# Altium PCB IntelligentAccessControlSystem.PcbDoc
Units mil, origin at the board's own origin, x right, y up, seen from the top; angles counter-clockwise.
Board outline 3020 x 3355 mil, 2 copper layers (Top Layer, Bottom Layer); 10 components, 8 nets, 88 pads, 0 vias.
Unrouted connection lines stored in the file: 2.
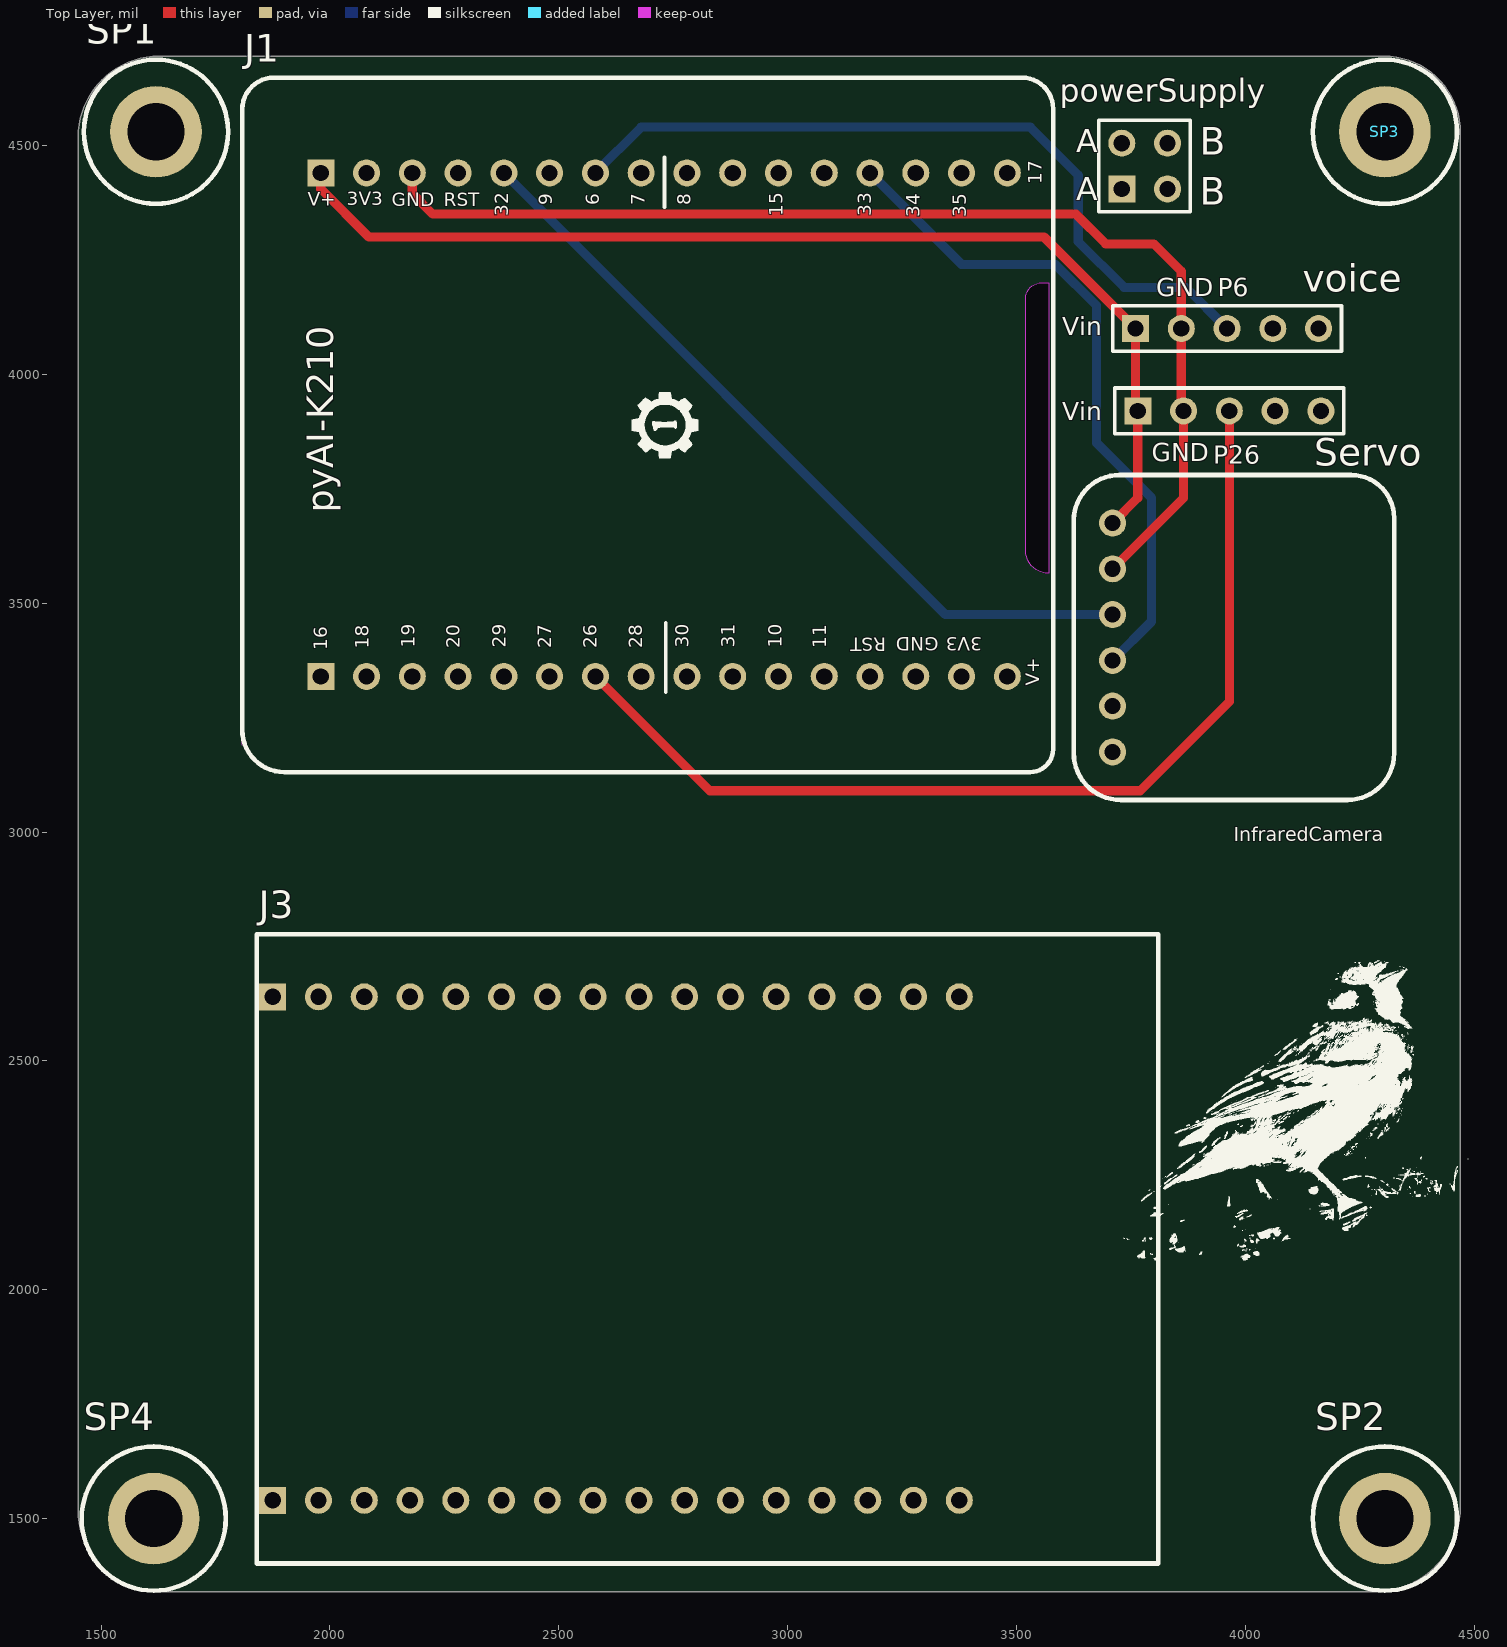
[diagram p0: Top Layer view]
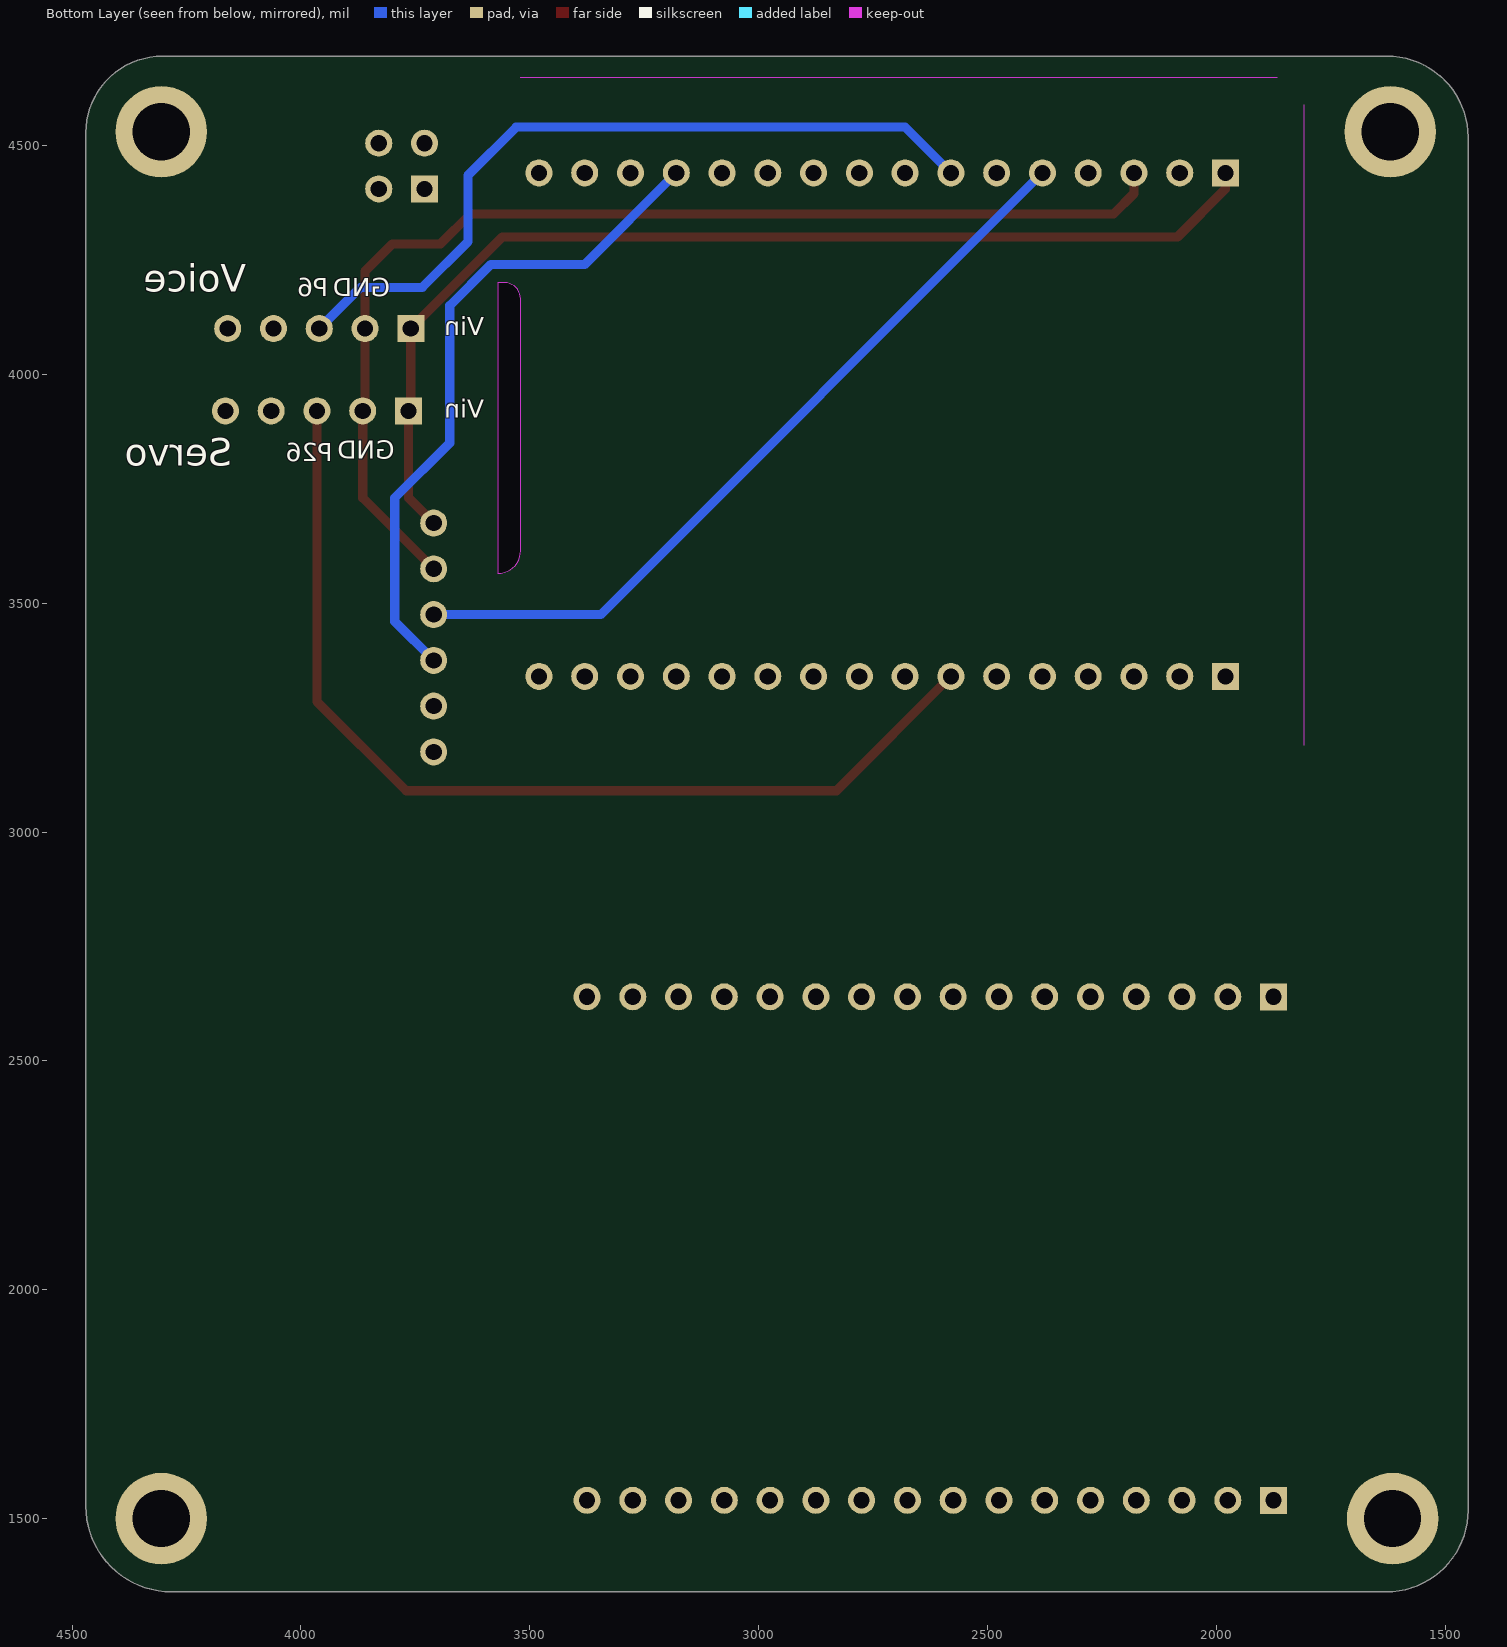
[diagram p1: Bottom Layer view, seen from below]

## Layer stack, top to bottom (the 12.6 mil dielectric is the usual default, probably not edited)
Top Solder: solder mask 0.4, Solder Resist, Dk 3.5
Top Layer: signal copper 1.4
Dielectric 1: dielectric 12.6, FR-4, Dk 4.8
Bottom Layer: signal copper 1.4
Bottom Solder: solder mask 0.4, Solder Resist, Dk 3.5

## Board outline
1450,1518.48 1450,4517.89 cw(c1627.11,4517.89) 1627.11,4695 4302.55,4695 cw(c4302.55,4527.55) 4470,4527.55 4470,1527.46 cw(c4282.54,1527.46) 4282.54,1340 1628.48,1340 cw(c1628.48,1518.48)
cut-out: 3570,3565 cw(c3570,3615) 3520,3615 3520,4165 cw(c3555,4165) 3555,4200 3570,4200

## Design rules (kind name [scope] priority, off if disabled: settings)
Clearance [All] p1: gap=10 ignorepadtopadclearanceinfootprint=FALSE except(0: Arc-Hole Track-Hole SMDPad-Hole THPad-Hole Via-Hole Fill-Hole Poly-Hole Region-Hole Text-Hole)
PolygonConnect [All] p1: connectstyle=Relief reliefconductorwidth=10 reliefentries=4 polygonreliefangle="90 Angle" airgapwidth=10
RoutingVias [All] p1: holewidth=28 width=50 viastyle="Through Hole" minholewidth=28 minwidth=50 maxholewidth=28 maxwidth=50
SolderMaskExpansion [All] p1: expansion=4
Width [All] p1: maxlimit=30 minlimit=20 preferedwidth=20 minimp=50.000000 maximp=50.000000 favimp=50.000000
30 further rules are at their usual default settings.

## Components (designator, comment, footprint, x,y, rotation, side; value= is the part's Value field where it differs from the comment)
InfraredCamera "InfraredCamera" InfraredCamera 3620,3795 r270 top (schematic designator J2)
J1 "K210-Main-Board" K210-Main-Board 2730,3890 r90 top
J3 "LCD" LCD 3810,1401.78 r90 top
powerSupply "Additional power supply" HDR2X2 3730,4405 r0 top (schematic designator P2)
Servo "Servo" HDR1X5 3765,3920 r0 top (schematic designator P3)
SP1 "M3铜柱" M3x4_L 1620,4530 r0 top
SP2 "M3铜柱" M3x4_L 4305,1500 r0 top
SP3 "M3铜柱" M3x4_L 4305,4530 r0 top
SP4 "M3铜柱" M3x4_L 1615,1500 r0 top
voice "voice broadcast" HDR1X5 3760,4100 r0 top (schematic designator P1)

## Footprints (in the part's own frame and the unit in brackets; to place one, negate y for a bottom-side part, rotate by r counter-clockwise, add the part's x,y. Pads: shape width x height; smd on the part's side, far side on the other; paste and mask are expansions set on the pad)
HDR1X5 [mm] "Connector; Header; 5 Position"
  rect 1.5x1.5 hole 0.9: 1(0,0)
  round 1.5 hole 0.9: 2(2.54,0) 3(5.08,0) 4(7.62,0) 5(10.16,0)
  silkscreen extent -1.27,-1.27 11.43,1.27
HDR2X2 [mm] "Connector; Header; 2x2 Position"
  rect 1.5x1.5 hole 0.9: 1(0,0)
  round 1.5 hole 0.9: 2(0,2.54) 3(2.54,0) 4(2.54,2.54)
  silkscreen extent -1.27,-1.27 3.81,3.81
InfraredCamera [mm]
  round 1.5 hole 0.9: 1(3.048,2.286) 2(5.588,2.286) 3(8.128,2.286) 4(10.668,2.286) 5(13.208,2.286) 6(15.748,2.286)
  silkscreen extent 0.38,0.13 18.41,17.91
K210-Main-Board [mm]
  rect 1.5x1.5 hole 0.9: 1(-13.97,19.05) 32(13.97,19.05)
  round 1.5 hole 0.9: 2(-13.97,16.51) 3(-13.97,13.97) 4(-13.97,11.43) 5(-13.97,8.89) 6(-13.97,6.35) 7(-13.97,3.81) 8(-13.97,1.27) 9(-13.97,-1.27) 10(-13.97,-3.81) 11(-13.97,-6.35) 12(-13.97,-8.89) 13(-13.97,-11.43) 14(-13.97,-13.97) 15(-13.97,-16.51) 16(-13.97,-19.05) 17(13.97,-19.05) 18(13.97,-16.51) 19(13.97,-13.97) 20(13.97,-11.43) 21(13.97,-8.89) 22(13.97,-6.35) 23(13.97,-3.81) 24(13.97,-1.27) 25(13.97,1.27) 26(13.97,3.81) 27(13.97,6.35) 28(13.97,8.89) 29(13.97,11.43) 30(13.97,13.97) 31(13.97,16.51)
  Keep-Out Layer lines w0: -17.779,23.41 17.761,23.41 ; 19.261,21.91 19.261,-20.09
  silkscreen extent -19.28,-21.59 19.26,23.41
LCD [mm]
  rect 1.5x1.5 hole 0.9: 1(3.511,49.149) 32(31.451,49.149)
  round 1.5 hole 0.9: 2(3.511,46.609) 3(3.511,44.069) 4(3.511,41.529) 5(3.511,38.989) 6(3.511,36.449) 7(3.511,33.909) 8(3.511,31.369) 9(3.511,28.829) 10(3.511,26.289) 11(3.511,23.749) 12(3.511,21.209) 13(3.511,18.669) 14(3.511,16.129) 15(3.511,13.589) 16(3.511,11.049) 17(31.451,11.049) 18(31.451,13.589) 19(31.451,16.129) 20(31.451,18.669) 21(31.451,21.209) 22(31.451,23.749) 23(31.451,26.289) 24(31.451,28.829) 25(31.451,31.369) 26(31.451,33.909) 27(31.451,36.449) 28(31.451,38.989) 29(31.451,41.529) 30(31.451,44.069) 31(31.451,46.609)
  silkscreen extent 0,0 34.92,50.04
M3x4_L [mil] "M3铜柱，长：4mm"
  round 200 hole 125: 1(0,0)
  silkscreen extent -157,-157 157,157, body extent -106,-93 106,93, height 159

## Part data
powerSupply: library part "Header 2X2", "Header, 2-Pin, Dual row"
Servo voice: library part "Header 5", "Header, 5-Pin"
SP1 SP2 SP3 SP4: library part 铜柱小焊盘, "铜柱"

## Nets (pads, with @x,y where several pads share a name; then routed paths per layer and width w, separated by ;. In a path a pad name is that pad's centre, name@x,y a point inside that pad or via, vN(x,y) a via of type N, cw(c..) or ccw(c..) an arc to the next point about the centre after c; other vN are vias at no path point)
6: J1.26 voice.3 | length 1688.6
  Bottom Layer w20: J1.26 2680,4540 3530,4540 3635,4435 3635,4290 3735,4190 3870,4190 voice.3
26: J1.7 Servo.3 | length 2204.3
  Top Layer w20: J1.7 2830,3090 3770,3090 3965,3285 Servo.3
GND: InfraredCamera.2 J1.30 Servo.2 voice.2 | length 2511.7
  Top Layer w20: J1.30 2180,4395 2225,4350 3630,4350 3695,4285 3800,4285 3860,4225 voice.2 3860,3925 Servo.2 3865,3730 InfraredCamera.2
NetP2_1: powerSupply.1 powerSupply.2
NetP2_3: powerSupply.3 powerSupply.4
SCL: InfraredCamera.3 J1.28 | length 1729.7
  Bottom Layer w20: J1.28 3345,3475 InfraredCamera.3
SDA: InfraredCamera.4 J1.20 | length 1475
  Bottom Layer w20: J1.20 3380,4240 3585,4240 3675,4150 3675,3850 3795,3730 3795,3460 InfraredCamera.4
Vin: InfraredCamera.1 J1.32 Servo.1 voice.1 | length 2391.2
  Top Layer w20: J1.32 1980,4405 2085,4300 3560,4300 voice.1 3760,3925 Servo.1 3765,3730 InfraredCamera.1
pads on no net: InfraredCamera.5 InfraredCamera.6 J1.1 J1.2 J1.3 J1.4 J1.5 J1.6 J1.8 J1.9 J1.10 J1.11 J1.12 J1.13 J1.14 J1.15 J1.16 J1.17 J1.18 J1.19 J1.21 J1.22 J1.23 J1.24 J1.25 J1.27 J1.29 J1.31 J3.1 J3.2 J3.3 J3.4 J3.5 J3.6 J3.7 J3.8 J3.9 J3.10 J3.11 J3.12 J3.13 J3.14 J3.15 J3.16 J3.17 J3.18 J3.19 J3.20 J3.21 J3.22 J3.23 J3.24 J3.25 J3.26 J3.27 J3.28 J3.29 J3.30 J3.31 J3.32 Servo.4 Servo.5 SP1.1 SP2.1 SP3.1 SP4.1 voice.4 voice.5

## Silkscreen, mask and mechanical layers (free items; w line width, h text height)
Top Overlay:
  drawing of 5566 lines, arcs and shapes, not listed
  text "B" at 3900,4480 h60
  text "GND" at 3805,4170 h40
  text "P6" at 3940,4170 h40
  text "Vin" at 3600,4085 h40
  text "Vin" at 3600,3900 h40
  text "GND" at 3795,3810 h40
  text "P26" at 3930,3805 h40
Bottom Overlay:
  text "Voice" at 4120,4180 h60
  text "GND" at 3805,4170 h40
  text "P6" at 3940,4170 h40
  text "Vin" at 3600,4085 h40
  text "Vin" at 3600,3905 h40
  text "GND" at 3795,3815 h40
  text "P26" at 3930,3810 h40
  text "Servo" at 4150,3800 h60
Mechanical 1:
  lines w10: 1450,1518.48 ccw(c1628.48,1518.48) 1628.48,1340 4175,1340 4282.54,1340 ccw(c4282.54,1527.46) 4470,1527.46 4470,4400 4470,4527.55 ccw(c4302.55,4527.55) 4302.55,4695 1910,4695 1627.11,4695 ccw(c1627.11,4517.89) 1450,4517.89 1450,3700 1450,1518.48 ; 3520,3615 ccw(c3570,3615) 3570,3565 3570,4200 3555,4200 ccw(c3555,4165) 3520,4165 3520,3615 ; 3740,1750 ccw(c3790,1750) 3790,1700 3790,2335 3775,2335 ccw(c3775,2300) 3740,2300 3740,1750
